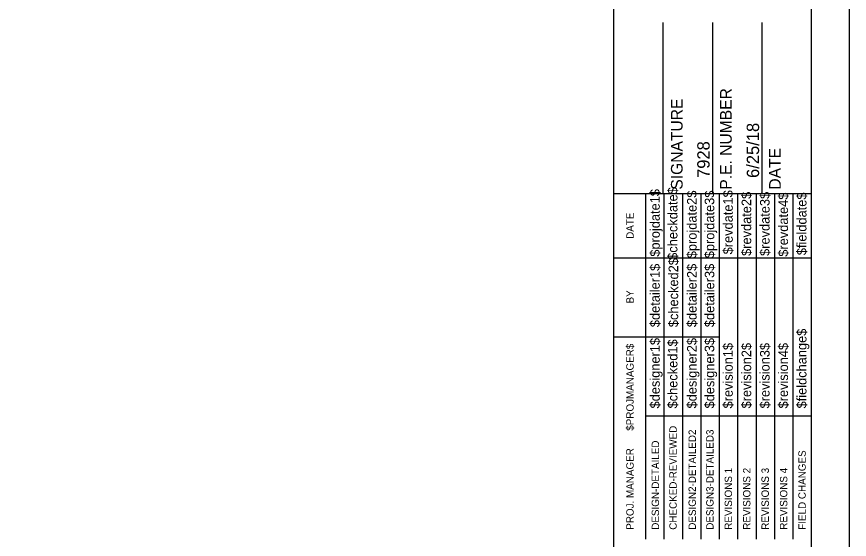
# Model space of a CAD drawing. Extents: x 9916 to 916479, y 6678 to 329942.
# Drawn here: x 916260.7 to 916471.2, y 329632 to 329764.2 of the extents above; entities that cross this region are included whole.
import ezdxf

# ---------------------------------------------------------------- set-up
doc = ezdxf.new("R2010")
doc.units = 0
doc.layers.add('Border', color=7, linetype='Continuous')
doc.layers.add('PLOT BOUNDARY', color=7, linetype='Continuous')

msp = doc.modelspace()

# ---------------------------------------------------------------- linework, layer by layer
at = {"layer": 'Border'}
for p, q in [((916411.64, 329407.01), (916411.64, 329932.01)), ((916461.64, 329407.01), (916461.64, 329932.01)), ((916424.14, 329719.51), (916424.14, 329762.75)), ((916436.64, 329719.51), (916436.64, 329762.75)), ((916449.14, 329719.51), (916449.14, 329762.75)), ((916411.64, 329719.51), (916461.64, 329719.51))]:
    msp.add_line(p, q, dxfattribs=at)
for points in [[(916419.71, 329703.26), (916419.71, 329719.51)], [(916424.37, 329632.03), (916424.37, 329719.51)], [(916429.03, 329719.51), (916429.03, 329632.03)], [(916433.69, 329632.03), (916433.69, 329719.51)], [(916438.35, 329632.03), (916438.35, 329719.51)], [(916443.01, 329632.03), (916443.01, 329719.51)], [(916447.67, 329632.03), (916447.67, 329719.51)], [(916452.32, 329632.03), (916452.32, 329719.51)], [(916456.98, 329632.03), (916456.98, 329719.51)], [(916419.72, 329632.03), (916419.72, 329715.98)], [(916411.64, 329703.26), (916461.64, 329703.26)], [(916411.64, 329683.26), (916419.72, 329683.26)], [(916419.71, 329683.26), (916438.34, 329683.26)], [(916419.71, 329663.26), (916461.64, 329663.26)]]:
    msp.add_lwpolyline(points, dxfattribs=at)
at = {"layer": 'PLOT BOUNDARY'}
msp.add_lwpolyline([(915621.17, 329391.7), (916471.17, 329391.7), (916471.17, 329941.7), (915621.17, 329941.7)], close=True, dxfattribs=at)

# ---------------------------------------------------------------- texts
at = {"layer": 'Border'}
for s, height, p in [('P.E. NUMBER', 2.9528, (916441.44, 329720.47)), ('SIGNATURE', 2.953, (916429.04, 329720.47)), ('6/25/18', 3.125, (916448.36, 329723.43)), ('7928', 3.125, (916435.86, 329723.43)), ('DATE', 2.953, (916453.84, 329720.47)), ('$projdate1$', 2.4227, (916423.25, 329703.51)), ('$checkdate$', 2.4227, (916427.72, 329702.72)), ('$projdate2$', 2.4227, (916432.57, 329703.12)), ('$projdate3$', 2.4227, (916437.04, 329703.12)), ('$revdate1$', 2.423, (916441.7, 329704.1)), ('$revdate2$', 2.423, (916446.36, 329703.71)), ('$revdate3$', 2.423, (916451.01, 329703.71)), ('$revdate4$', 2.423, (916455.67, 329703.51)), ('$fielddate$', 2.4227, (916460.33, 329703.9)), ('DATE', 1.857, (916416.66, 329708.04)), ('$checked2$', 2.423, (916427.91, 329685.69)), ('$detailer1$', 2.4227, (916423.25, 329685.69)), ('$detailer2$', 2.4227, (916432.57, 329685.69)), ('$detailer3$', 2.4227, (916437.04, 329685.69)), ('BY', 1.857, (916416.66, 329691.69)), ('$fieldchange$', 2.4227, (916460.33, 329665.13)), ('$PROJMANAGER$', 1.8637, (916416.66, 329659.49)), ('$designer1$', 2.4227, (916423.25, 329665.13)), ('$checked1$', 2.423, (916427.72, 329665.13)), ('$designer2$', 2.4227, (916432.57, 329665.13)), ('$designer3$', 2.4227, (916437.04, 329665.13)), ('$revision1$', 2.4227, (916441.7, 329665.13)), ('$revision2$', 2.4227, (916446.36, 329665.13)), ('$revision3$', 2.4227, (916451.01, 329665.13)), ('$revision4$', 2.4227, (916455.67, 329665.13)), ('CHECKED-REVIEWED', 1.8637, (916427.54, 329634.45)), ('DESIGN2-DETAILED2', 1.8637, (916432.39, 329634.45)), ('DESIGN3-DETAILED3', 1.8637, (916436.86, 329634.45)), ('DESIGN-DETAILED', 1.8637, (916423.07, 329634.45)), ('PROJ. MANAGER', 1.8637, (916416.66, 329634.45)), ('FIELD CHANGES', 1.8637, (916460.15, 329634.45)), ('REVISIONS 1', 1.8637, (916441.52, 329634.45)), ('REVISIONS 2', 1.8637, (916446.17, 329634.45)), ('REVISIONS 3', 1.8637, (916450.83, 329634.45)), ('REVISIONS 4', 1.8637, (916455.49, 329634.45))]:
    msp.add_text(s, height=height, rotation=90, dxfattribs=at).set_placement(p)

doc.saveas('drawing.dxf')
